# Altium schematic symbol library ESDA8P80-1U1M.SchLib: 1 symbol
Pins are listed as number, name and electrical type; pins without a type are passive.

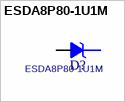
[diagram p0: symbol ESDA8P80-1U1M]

## ESDA8P80-1U1M
designator D?
footprint ST_1610
pins: 1 K, 2 A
